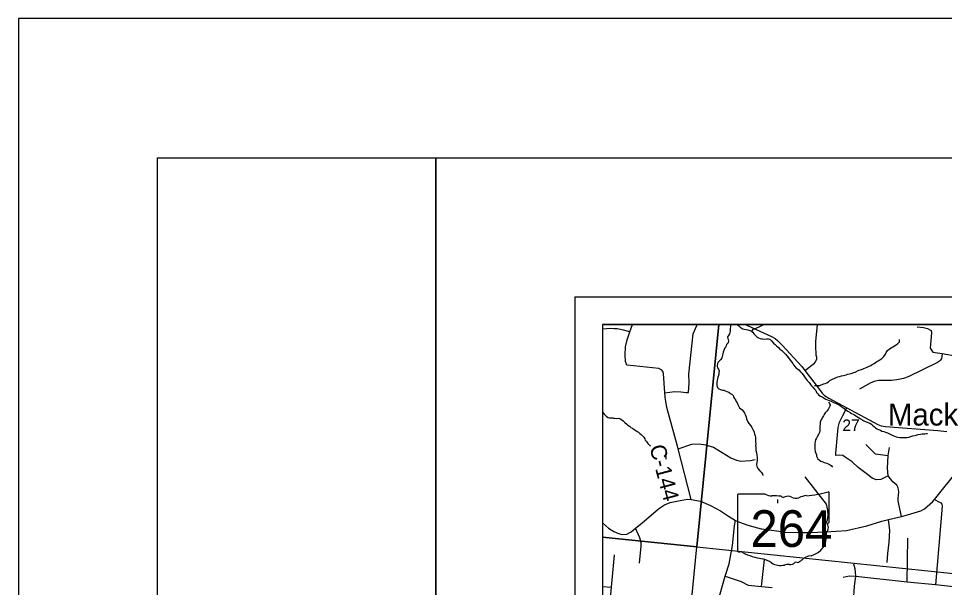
# Model space of a CAD drawing. Extents: x 0 to 34, y -2 to 22.
# Drawn here: x 0 to 3.329, y 19.956 to 22 of the extents above; entities that cross this region are included whole.
import ezdxf

# ---------------------------------------------------------------- set-up
doc = ezdxf.new("R2010")
doc.units = 0
for name, color, linetype in [('Default', 7, 'Continuous'), ('GM_X_County_Road', 7, 'Continuous'), ('GM_X_County_Road_Text', 7, 'Continuous'), ('GM_X_Minor_River', 7, 'Continuous'), ('GM_X_Rail_Line', 7, 'Continuous'), ('GM_X_Section', 7, 'Continuous'), ('GM_X_Section_Text', 7, 'Continuous'), ('GM_X_State_Location', 7, 'Continuous'), ('GM_X_State_Route', 7, 'Continuous'), ('GM_X_State_Shield', 7, 'Continuous'), ('GM_X_Township_Road', 7, 'Continuous'), ('GM_X_Unincorporated_Text', 7, 'Continuous'), ('SH_Border', 7, 'Continuous'), ('SH_Cut_Line', 7, 'Continuous'), ('SH_Data', 7, 'Continuous')]:
    doc.layers.add(name, color=color, linetype=linetype)

msp = doc.modelspace()

# ---------------------------------------------------------------- linework, layer by layer
at = {"layer": 'Default'}
for points in [[(2.5176, 20.9), (2.1, 20.9), (2.1, 20.1369), (2.4387, 20.1012)], [(3.5359, 20.9), (2.5176, 20.9), (2.4387, 20.1012), (3.4541, 19.9967)], [(2.1, 20.1369), (2.1, 19.1108), (2.3398, 19.083), (2.4387, 20.1012)]]:
    msp.add_lwpolyline(points, close=True, dxfattribs=at)
at = {"layer": 'GM_X_County_Road'}
for points in [[(2.3246, 20.6458), (2.3242, 20.6509), (2.3239, 20.6553), (2.3188, 20.7242), (2.3163, 20.7315), (2.3127, 20.7365), (2.3022, 20.7425), (2.1887, 20.755), (2.1873, 20.7556), (2.1862, 20.7566), (2.1854, 20.7581), (2.1822, 20.7677), (2.1806, 20.7913), (2.1825, 20.8209), (2.1881, 20.8458), (2.1978, 20.8748), (2.2078, 20.9)], [(2.6136, 20.9), (2.6207, 20.8975), (2.7069, 20.8572), (2.7201, 20.8504), (2.7293, 20.8433), (2.7456, 20.8269), (2.816, 20.7495), (2.8273, 20.7348), (2.8798, 20.6665), (2.8889, 20.6537), (2.8978, 20.6451), (2.9132, 20.6363), (2.9785, 20.6012)], [(2.4184, 20.2713), (2.3719, 20.4535), (2.3694, 20.4634), (2.3314, 20.6019), (2.3284, 20.6176), (2.3252, 20.6378), (2.3246, 20.6458)], [(2.9785, 20.6012), (3.0897, 20.5413), (3.1017, 20.5364), (3.1176, 20.5345), (3.3055, 20.5196), (3.3376, 20.5164)], [(2.3338, 19.4483), (2.3443, 19.4595), (2.3661, 19.4889), (2.3697, 19.4957), (2.3732, 19.515), (2.3798, 19.5908), (2.3832, 19.631), (2.3882, 19.6456), (2.3969, 19.6595), (2.4454, 19.7543), (2.4712, 19.808), (2.4732, 19.813), (2.5131, 19.8995), (2.5409, 19.9962), (2.5554, 20.0405), (2.5666, 20.106), (2.5737, 20.177), (2.5781, 20.1967)]]:
    msp.add_lwpolyline(points, dxfattribs=at)
at = {"layer": 'GM_X_Minor_River'}
for points in [[(2.5593, 20.9), (2.5594, 20.8943), (2.5591, 20.8852), (2.5585, 20.8788), (2.5575, 20.8712), (2.5562, 20.8667), (2.5526, 20.8615), (2.5494, 20.8563), (2.5499, 20.8502), (2.5513, 20.8452), (2.553, 20.8402), (2.5509, 20.8353), (2.5458, 20.829), (2.5437, 20.8238), (2.5413, 20.8193), (2.5385, 20.8145), (2.5356, 20.8077), (2.533, 20.8006), (2.5317, 20.7949), (2.5308, 20.7904), (2.5303, 20.7859), (2.5282, 20.7814), (2.5253, 20.7754), (2.5206, 20.7702), (2.5155, 20.7651), (2.5131, 20.7606), (2.5121, 20.7538), (2.5123, 20.7493), (2.5136, 20.7443), (2.5165, 20.7396), (2.5186, 20.7342), (2.5184, 20.7285), (2.5174, 20.7228), (2.5161, 20.7168), (2.5148, 20.7119), (2.513, 20.7051), (2.5121, 20.7002), (2.5107, 20.6927), (2.5105, 20.6866), (2.5107, 20.6817), (2.5131, 20.6744), (2.5175, 20.6696), (2.5239, 20.6668), (2.531, 20.6646), (2.5356, 20.6645), (2.5412, 20.6627), (2.5472, 20.6603), (2.5539, 20.6577), (2.5595, 20.653), (2.5643, 20.6502), (2.5691, 20.6458), (2.5712, 20.6408), (2.5744, 20.6346), (2.5776, 20.6299), (2.5808, 20.6237), (2.5841, 20.6187), (2.5858, 20.6133), (2.5883, 20.6083), (2.5922, 20.6017), (2.5974, 20.5973), (2.6018, 20.5941), (2.6062, 20.5883), (2.6105, 20.582), (2.6126, 20.5767), (2.6161, 20.5674), (2.6174, 20.5617), (2.6199, 20.5555), (2.622, 20.5505), (2.6263, 20.5443), (2.6325, 20.5368), (2.6361, 20.5306), (2.6404, 20.5229), (2.6447, 20.5147), (2.6467, 20.5071), (2.6484, 20.5009), (2.6493, 20.496), (2.6499, 20.4906), (2.6501, 20.4845), (2.6503, 20.4792), (2.6504, 20.472), (2.6502, 20.4655), (2.6504, 20.4602), (2.651, 20.4552), (2.6515, 20.448), (2.6531, 20.4403), (2.6543, 20.4315), (2.6555, 20.422), (2.6561, 20.417), (2.6559, 20.4125), (2.655, 20.4061), (2.6539, 20.397), (2.6541, 20.3909), (2.6576, 20.3835), (2.6653, 20.3753), (2.6697, 20.3698), (2.6744, 20.3643), (2.6761, 20.3586), (2.6763, 20.3577)], [(2.5833, 20.9), (2.588, 20.8968), (2.5943, 20.8916), (2.5987, 20.8888), (2.6039, 20.8856), (2.6092, 20.8839), (2.6156, 20.8829), (2.6216, 20.8815), (2.6295, 20.8786), (2.6351, 20.8761), (2.6403, 20.8725), (2.6443, 20.8667), (2.6505, 20.8596), (2.6556, 20.8549), (2.6609, 20.8528), (2.6665, 20.8507), (2.6718, 20.8494), (2.6763, 20.8485), (2.6816, 20.8479), (2.69, 20.8491), (2.6968, 20.8493), (2.7013, 20.8476), (2.7076, 20.8421), (2.7145, 20.8339), (2.72, 20.8283), (2.7252, 20.8244), (2.7326, 20.8176), (2.7377, 20.8125), (2.7447, 20.8066), (2.7517, 20.7999), (2.7576, 20.7944), (2.7634, 20.7869), (2.7681, 20.7811), (2.7743, 20.7725), (2.779, 20.7666), (2.7834, 20.7604), (2.7862, 20.7557), (2.7906, 20.7499), (2.7957, 20.744), (2.8002, 20.7416), (2.8054, 20.7372), (2.8116, 20.7309), (2.816, 20.7258), (2.8207, 20.72), (2.8261, 20.7126), (2.8323, 20.704), (2.8359, 20.6989), (2.8421, 20.6919), (2.8472, 20.6852), (2.8516, 20.6805), (2.856, 20.6754), (2.8618, 20.6688), (2.8662, 20.6637), (2.8694, 20.6563), (2.8734, 20.6516), (2.877, 20.6469), (2.8834, 20.6433), (2.889, 20.6405), (2.8968, 20.636), (2.902, 20.6324), (2.9091, 20.6299), (2.9147, 20.6274), (2.9214, 20.6249), (2.93, 20.6204), (2.9379, 20.6175), (2.9446, 20.6138), (2.9495, 20.6121), (2.954, 20.6101), (2.9599, 20.6053), (2.9643, 20.6025), (2.9691, 20.5989), (2.9739, 20.5942), (2.9821, 20.5893), (2.9899, 20.5841), (2.9951, 20.5813), (3.0003, 20.5788), (3.0052, 20.5764), (3.0108, 20.5728), (3.0167, 20.5691), (3.0226, 20.5648)], [(2.6356, 20.8758), (2.6422, 20.8841), (2.6525, 20.888), (2.6648, 20.8933), (2.6772, 20.8994), (2.6784, 20.9)], [(2.8623, 20.6817), (2.871, 20.681), (2.8759, 20.6812), (2.8809, 20.6818), (2.8863, 20.6835), (2.8955, 20.6874), (2.9001, 20.6887), (2.9059, 20.6912), (2.9121, 20.6948), (2.9168, 20.6995), (2.9269, 20.7045), (2.9349, 20.708), (2.9403, 20.7101), (2.9461, 20.7122), (2.9515, 20.7132), (2.9588, 20.7163), (2.9657, 20.7176), (2.9752, 20.7196), (2.9821, 20.722), (2.994, 20.7246), (3.0032, 20.7285), (3.0078, 20.7298), (3.0217, 20.7362), (3.0263, 20.7379), (3.0309, 20.7393), (3.0398, 20.7424), (3.0452, 20.7445), (3.051, 20.747), (3.056, 20.7495), (3.0641, 20.7537), (3.0695, 20.757), (3.0761, 20.7605), (3.0808, 20.7642), (3.0862, 20.7674), (3.0912, 20.7699), (3.0967, 20.7739), (3.104, 20.7782), (3.1111, 20.7856), (3.1171, 20.7945), (3.1196, 20.8005), (3.1244, 20.8068), (3.1311, 20.813), (3.1439, 20.8209), (3.1497, 20.8241), (3.1551, 20.8277), (3.161, 20.8321), (3.1672, 20.838), (3.1679, 20.8471)], [(2.9126, 20.6214), (2.9159, 20.6167), (2.9187, 20.6113), (2.9174, 20.6068), (2.915, 20.6023), (2.9113, 20.5952), (2.9062, 20.5897), (2.9006, 20.583), (2.897, 20.5767), (2.8938, 20.5719), (2.8898, 20.5655), (2.8877, 20.5611), (2.8849, 20.5566), (2.8828, 20.5502), (2.8822, 20.5426), (2.8816, 20.5362), (2.881, 20.5191), (2.8796, 20.5131), (2.8775, 20.5078), (2.8715, 20.4966), (2.8686, 20.4922), (2.8658, 20.4862), (2.8644, 20.479), (2.8635, 20.4745), (2.8629, 20.4677), (2.8626, 20.4604), (2.8628, 20.4559), (2.8634, 20.4509), (2.8647, 20.4444), (2.8668, 20.4379), (2.8685, 20.4325), (2.8695, 20.4275), (2.8712, 20.4229), (2.8741, 20.4179), (2.8796, 20.4131), (2.8848, 20.4099), (2.8915, 20.407), (2.8964, 20.4053), (2.9013, 20.4032), (2.9062, 20.4019), (2.911, 20.4002), (2.9177, 20.3958), (2.9222, 20.3938), (2.9269, 20.3883)], [(2.1, 20.5853), (2.1055, 20.579), (2.1095, 20.5743), (2.1143, 20.5696), (2.1202, 20.5667), (2.1248, 20.5654), (2.1297, 20.5648), (2.135, 20.5647), (2.1395, 20.5637), (2.1441, 20.5636), (2.149, 20.5634), (2.1558, 20.5636), (2.1619, 20.5626), (2.1686, 20.5586), (2.1737, 20.5546), (2.1803, 20.5479), (2.1866, 20.542), (2.1911, 20.5392), (2.1966, 20.5352), (2.2018, 20.5308), (2.2074, 20.528), (2.2133, 20.5236), (2.2196, 20.5192), (2.2241, 20.5164), (2.2289, 20.5135), (2.2344, 20.5084), (2.2392, 20.5056), (2.2436, 20.5005), (2.248, 20.4958), (2.252, 20.4895), (2.2533, 20.4849), (2.2581, 20.4802), (2.2624, 20.4732), (2.2698, 20.4657), (2.2723, 20.4641)], [(3.0226, 20.5648), (3.0271, 20.5619), (3.0353, 20.5567), (3.0398, 20.5547), (3.0472, 20.5514), (3.0566, 20.5472), (3.0611, 20.5456), (3.0663, 20.5427), (3.0718, 20.5376), (3.077, 20.5325), (3.0814, 20.5293), (3.0862, 20.5261), (3.0918, 20.5232), (3.0986, 20.5207), (3.1034, 20.5179), (3.1113, 20.5161), (3.1166, 20.514), (3.1241, 20.5118), (3.1293, 20.509), (3.1368, 20.5053), (3.1413, 20.5033), (3.1495, 20.4996), (3.1555, 20.4967), (3.1619, 20.4953), (3.1683, 20.4947), (3.1804, 20.4943), (3.1869, 20.4945), (3.1937, 20.495), (3.201, 20.4962), (3.2083, 20.4983), (3.2159, 20.5003), (3.2225, 20.502), (3.2274, 20.5033), (3.2347, 20.505), (3.2424, 20.5066), (3.2485, 20.5075), (3.2534, 20.5081), (3.2584, 20.5083), (3.2633, 20.5089), (3.2686, 20.5091)], [(2.3288, 20.4173), (2.3288, 20.4261)], [(2.73, 20.259), (2.7297, 20.2712)]]:
    msp.add_lwpolyline(points, dxfattribs=at)
at = {"layer": 'GM_X_Rail_Line'}
msp.add_lwpolyline([(7.5809, 20.9), (2.1, 20.9), (2.1, 18.1368), (2.3446, 18.1102), (2.9298, 18.0171), (3.2869, 17.9604), (3.6832, 17.9108)], dxfattribs=at)
at = {"layer": 'GM_X_Section'}
msp.add_lwpolyline([(3.4541, 19.9967), (3.3818, 18.9832), (2.3398, 19.083), (2.4387, 20.1012)], close=True, dxfattribs=at)
at = {"layer": 'GM_X_State_Route'}
msp.add_line((2.6728, 20.1661), (2.7521, 20.1556), dxfattribs=at)
for points in [[(2.7521, 20.1556), (2.756, 20.155), (2.8155, 20.1533), (2.8429, 20.1537), (2.9026, 20.1559), (2.9768, 20.1606), (3.05, 20.1771), (3.1038, 20.1937), (3.1276, 20.1996), (3.1742, 20.211), (3.1958, 20.2163), (3.2439, 20.2311), (3.2569, 20.2377), (3.2863, 20.2636), (3.2937, 20.2723), (3.3809, 20.3811), (3.4116, 20.4137)], [(2.1, 20.1875), (2.1217, 20.1685), (2.14, 20.1563), (2.1569, 20.1491), (2.1704, 20.1457), (2.1868, 20.1476), (2.2029, 20.1552), (2.2188, 20.1682), (2.2411, 20.1862), (2.3011, 20.2377), (2.3231, 20.2531), (2.3426, 20.2606), (2.3792, 20.2678), (2.4058, 20.2725), (2.4184, 20.2713), (2.4519, 20.2657), (2.488, 20.2504), (2.5239, 20.2306), (2.5531, 20.2124)], [(2.5531, 20.2124), (2.5781, 20.1967), (2.5923, 20.1899), (2.622, 20.1798), (2.6699, 20.1665), (2.6728, 20.1661)]]:
    msp.add_lwpolyline(points, dxfattribs=at)
at = {"layer": 'GM_X_State_Shield'}
for p, q in [((2.5851, 20.2874), (2.5851, 20.0873)), ((2.6849, 20.2909), (2.5884, 20.2909)), ((2.9147, 20.1912), (2.9147, 20.2958)), ((2.9147, 20.1912), (2.9147, 20.1912))]:
    msp.add_line(p, q, dxfattribs=at)
for centre, major_axis, start_param, end_param in [((2.5889, 20.2879), (0.00382, 0), 1.712693, 3.28349), ((2.7079, 20.3141), (0.037, 0), 4.042523, 4.731795), ((2.7202, 20.1785), (0.133, 0), 1.404758, 1.657858), ((2.7504, 20.2889), (0.0107, 0), 3.836095, 5.185415), ((2.766, 20.2658), (0.0222, 0), 0.950623, 2.079405), ((2.7947, 20.2975), (0.0267, 0), 4.081561, 5.145723), ((2.8419, 20.2298), (0.0703, 0), 1.699011, 2.107814), ((2.7973, 20.5637), (0.3495, 0), 4.814394, 5.042369), ((2.9111, 20.2963), (0.00367, 0), 6.141152, 7.989035), ((2.9139, 20.1835), (0.00568, 0), 1.883978, 3.671073), ((2.8778, 20.1702), (0.0341, 0), 5.934695, 6.695948), ((2.9108, 20.1908), (0.00393, 0), 5.05454, 6.418171), ((2.8169, 20.134), (0.0874, 0), 5.101752, 6.440018), ((2.9279, 20.1473), (0.0248, 0), 2.387724, 3.262537), ((2.589, 20.0869), (0.00385, 0), 3.00124, 4.508301), ((2.5895, 20.1074), (0.0294, 0), 4.665946, 4.897461), ((2.5956, 20.0758), (0.0106, 0), 0.519207, 1.627899), ((2.7294, 20.2556), (0.2524, 0), 4.195997, 4.488961), ((2.6541, 19.9974), (0.079, 0), 0.823519, 1.323587), ((2.7395, 20.0748), (0.0501, 0), 4.026481, 4.996735), ((2.7722, 20.0598), (0.0267, 0), 4.691044, 5.507374), ((2.7963, 20.0404), (0.00752, 0), 1.147584, 2.315152), ((2.7931, 20.0679), (0.0282, 0), 4.937069, 5.64225), ((2.8538, 20.0311), (0.0479, 0), 1.647645, 2.488434), ((2.7685, 20.0056), (0.0412, 0), 1.495662, 1.94098)]:
    msp.add_ellipse(centre, major_axis=major_axis, ratio=0.8, start_param=start_param, end_param=end_param, dxfattribs=at)
at = {"layer": 'GM_X_Township_Road'}
for p, q in [((3.1945, 19.9751), (3.1974, 20.1323)), ((2.6711, 19.9594), (2.6822, 20.0566)), ((2.1, 19.9594), (2.1325, 19.9567))]:
    msp.add_line(p, q, dxfattribs=at)
for points in [[(2.1978, 20.8748), (2.1699, 20.8819), (2.152, 20.8846), (2.1417, 20.8855), (2.1287, 20.8865), (2.1, 20.8843)], [(2.3239, 20.6553), (2.3596, 20.6597), (2.3815, 20.659), (2.401, 20.6561), (2.4088, 20.6559), (2.4113, 20.6913), (2.4098, 20.7226), (2.4256, 20.8672), (2.4392, 20.8966), (2.4337, 20.9)], [(2.8273, 20.7348), (2.862, 20.7622), (2.866, 20.7669), (2.8683, 20.7715), (2.8703, 20.777), (2.8702, 20.7817), (2.8682, 20.7905), (2.8683, 20.8008), (2.8664, 20.8126), (2.8662, 20.8237), (2.8671, 20.8392), (2.8727, 20.9)], [(3.2307, 20.8928), (3.2534, 20.8898), (3.2685, 20.8868), (3.2812, 20.8791), (3.2829, 20.8701), (3.2779, 20.8156), (3.2869, 20.8015), (3.3203, 20.7958)], [(3.3203, 20.7958), (3.3194, 20.7851), (3.3179, 20.778), (3.3151, 20.773), (3.3116, 20.7692), (3.3036, 20.7642), (3.1983, 20.712), (3.1818, 20.7067), (3.1582, 20.7014), (3.1383, 20.6994), (3.1187, 20.6989), (3.0914, 20.6992), (3.0766, 20.6963), (3.0624, 20.6897), (3.0238, 20.6682)], [(3.3203, 20.7958), (3.3745, 20.7868), (3.5214, 20.7752)], [(2.9727, 20.4241), (2.9639, 20.43), (2.9512, 20.4309), (2.9386, 20.4296), (2.9387, 20.4384), (2.9466, 20.5307), (2.9519, 20.5496), (2.9639, 20.5731), (2.9785, 20.6012)], [(2.3719, 20.4535), (2.4211, 20.4702), (2.4467, 20.4714), (2.4703, 20.4688), (2.4985, 20.4596), (2.5609, 20.4215), (2.582, 20.413), (2.5974, 20.4101), (2.6314, 20.4121), (2.6486, 20.415)], [(3.0464, 20.4697), (3.08, 20.4358), (3.1271, 20.43)], [(3.1742, 20.211), (3.1645, 20.2547), (3.1624, 20.2666), (3.1629, 20.2759), (3.1643, 20.2878), (3.1647, 20.2994), (3.1631, 20.3133), (3.1579, 20.3229), (3.1435, 20.3352), (3.1271, 20.3566), (3.1248, 20.3844), (3.1271, 20.43), (3.1312, 20.4592)], [(3.1271, 20.3566), (3.1007, 20.3439), (3.0835, 20.3428), (3.0692, 20.3484), (3.0519, 20.3612), (3.0191, 20.3872), (2.9968, 20.4068), (2.9762, 20.4218), (2.9727, 20.4241)], [(2.9026, 20.1559), (2.8994, 20.1759), (2.9086, 20.1982), (2.9113, 20.2137), (2.9099, 20.2329), (2.9045, 20.2552), (2.8288, 20.3537)], [(3.2937, 20.2723), (3.3116, 20.2624), (3.3164, 20.2599), (3.3197, 20.2545), (3.3206, 20.2473), (3.2971, 19.9647)], [(3.1226, 20.0453), (3.1257, 20.0776), (3.1306, 20.1185), (3.1325, 20.1606), (3.1276, 20.1996)], [(2.2332, 20.0429), (2.2385, 20.1042), (2.2385, 20.1163), (2.2335, 20.1341), (2.2188, 20.1682)], [(2.1, 19.7592), (2.1033, 19.7645), (2.114, 19.7875), (2.1183, 19.8101), (2.1325, 19.9567), (2.1345, 19.982), (2.1433, 20.0729)], [(2.9982, 19.8642), (3.0002, 19.8856), (3.0015, 19.9057), (3.0062, 19.9605), (3.0101, 19.9946), (3.0092, 20.0115), (3.008, 20.0229), (3.0037, 20.0394)], [(2.5409, 19.9962), (2.5982, 19.9776), (2.6237, 19.9635), (2.6711, 19.9594), (2.7094, 19.9557)], [(3.4481, 19.9478), (3.2971, 19.9647), (3.1945, 19.9751), (3.0101, 19.9946), (2.9863, 19.9958), (2.9649, 19.9918)]]:
    msp.add_lwpolyline(points, dxfattribs=at)
at = {"layer": 'SH_Border'}
for points in [[(0.5, 21.5), (1.5, 21.5), (1.5, 0.5), (0.5, 0.5)], [(1.5, 21.5), (33.5, 21.5), (33.5, 0.5), (1.5, 0.5)]]:
    msp.add_lwpolyline(points, close=True, dxfattribs=at)
at = {"layer": 'SH_Cut_Line'}
msp.add_lwpolyline([(0, 0), (34, 0), (34, 22), (0, 22)], close=True, dxfattribs=at)
msp.add_lwpolyline([(8.9, 20.9), (2.1, 20.9), (2.1, 16.3648), (2.1342, 16.3571), (2.2291, 16.3515), (2.5217, 16.3621), (2.6166, 16.3275), (2.9069, 16.2111), (3.202, 16.0321), (3.297, 15.9555), (3.6339, 15.5717)], dxfattribs=at)
at = {"layer": 'SH_Data'}
for p, q in [((2, 21), (9, 21)), ((2, 21), (2, 14)), ((2.1, 20.9), (2.1, 14.1)), ((2.1, 20.9), (8.9, 20.9))]:
    msp.add_line(p, q, dxfattribs=at)

# ---------------------------------------------------------------- texts
at = {"layer": 'GM_X_County_Road_Text'}
msp.add_text('C-144', height=0.05682, rotation=284.8258, dxfattribs=at).set_placement((2.268, 20.461))
at = {"layer": 'GM_X_Section_Text'}
msp.add_text('27', height=0.04186, rotation=0, dxfattribs=at).set_placement((2.9619, 20.5176))
at = {"layer": 'GM_X_State_Location'}
msp.add_text('264', height=0.000189, rotation=0, dxfattribs=at).set_placement((2.6794, 20.1603))
for s in ['s', 'r']:
    msp.add_text(s, height=0.000189, dxfattribs=at).set_placement((2.7462, 20.1741))
at = {"layer": 'GM_X_State_Shield'}
msp.add_text('264', height=0.13184, dxfattribs=at).set_placement((2.6317, 20.1014))
at = {"layer": 'GM_X_Unincorporated_Text'}
msp.add_text('Mack', height=0.07898, rotation=0, dxfattribs=at).set_placement((3.126, 20.5375))

doc.saveas('drawing.dxf')
